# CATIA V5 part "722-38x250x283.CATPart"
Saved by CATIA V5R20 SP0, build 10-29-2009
Part number: 722-38x250x283
Definition: NONE
Nomenclature: 722-38x250x283
Source: Unknown
Description: 722-38x250x283
Bounding box of the stored display mesh (mm): x -19 to 19, y -19 to 19, z -235 to 48
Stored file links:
  C:\Users\Utente\Desktop\IO LAVORO\3D X SITO CF\X SITO\722\722-38x250x283.CATPart
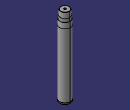
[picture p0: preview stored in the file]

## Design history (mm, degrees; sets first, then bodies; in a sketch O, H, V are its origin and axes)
Body1 "722-38x250x283" (main body)
  Solid1: solid without history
